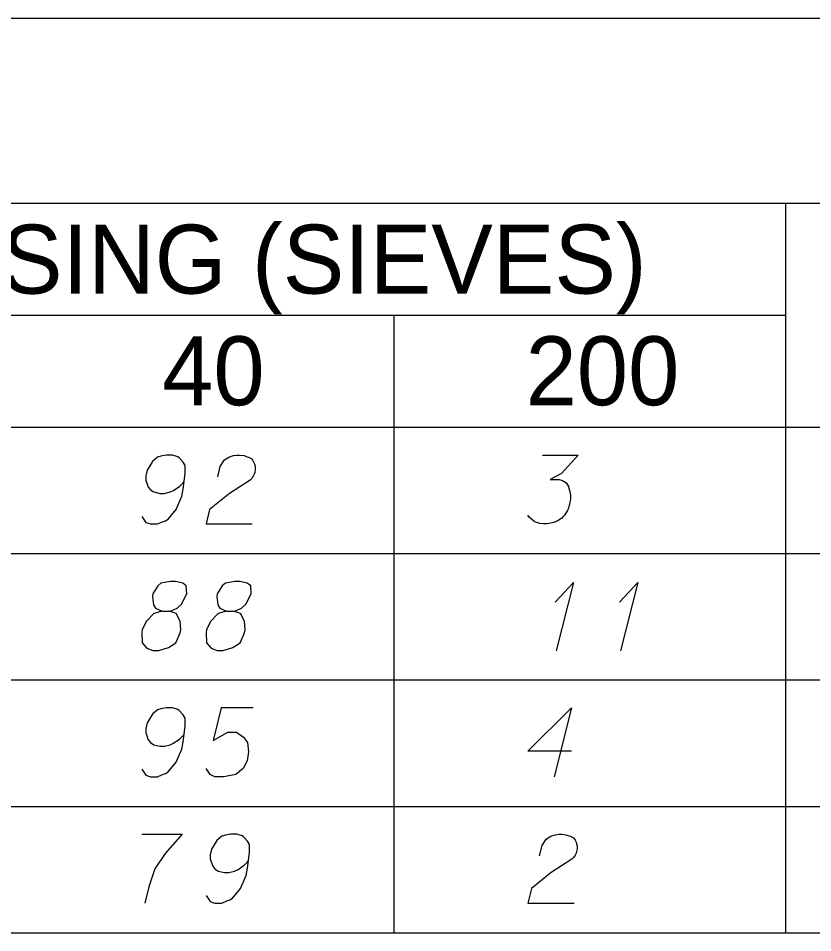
# Model space of a CAD drawing. Extents: x 2074207 to 2076812, y 516372 to 523312.
# Drawn here: x 2076678.5 to 2076733.8, y 516601.5 to 516665.2 of the extents above; entities that cross this region are included whole.
import ezdxf

# ---------------------------------------------------------------- set-up
doc = ezdxf.new("R2010")
doc.units = 0
for name, color, linetype in [('Prop DirtTable_ Soil Test Results - Outline (Major)', 7, 'Continuous'), ('Prop DirtTable_ Soil Test Results - Outline (Minor)', 7, 'Continuous'), ('Prop DirtTable_ Soil Test Results - Tx (Header - Small)', 7, 'Continuous'), ('Prop DirtTable_ Soil Test Results - Tx (Sample Data)', 7, 'Continuous')]:
    doc.layers.add(name, color=color, linetype=linetype)

msp = doc.modelspace()

# ---------------------------------------------------------------- linework, layer by layer
at = {"layer": 'Prop DirtTable_ Soil Test Results - Outline (Major)'}
for p, q in [((2076260.609, 516665.206), (2076811.903, 516665.206)), ((2076260.609, 516636.721), (2076811.903, 516636.721)), ((2076260.609, 516636.721), (2076811.903, 516636.721)), ((2076260.609, 516601.521), (2076811.903, 516601.521))]:
    msp.add_line(p, q, dxfattribs=at)
at = {"layer": 'Prop DirtTable_ Soil Test Results - Outline (Minor)'}
for p, q in [((2076260.609, 516652.321), (2076811.903, 516652.321)), ((2076731.93, 516652.321), (2076731.93, 516627.921)), ((2076526.074, 516644.521), (2076731.93, 516644.521)), ((2076704.671, 516644.521), (2076704.671, 516627.921)), ((2076260.609, 516627.921), (2076811.903, 516627.921)), ((2076260.609, 516627.921), (2076811.903, 516627.921)), ((2076704.671, 516627.921), (2076704.671, 516619.121)), ((2076731.93, 516627.921), (2076731.93, 516619.121)), ((2076260.609, 516619.121), (2076811.903, 516619.121)), ((2076260.609, 516619.121), (2076811.903, 516619.121)), ((2076704.671, 516619.121), (2076704.671, 516610.321)), ((2076731.93, 516619.121), (2076731.93, 516610.321)), ((2076260.609, 516610.321), (2076811.903, 516610.321)), ((2076260.609, 516610.321), (2076811.903, 516610.321)), ((2076704.671, 516610.321), (2076704.671, 516601.521)), ((2076731.93, 516610.321), (2076731.93, 516601.521)), ((2076260.609, 516601.521), (2076811.903, 516601.521))]:
    msp.add_line(p, q, dxfattribs=at)
at = {"layer": 'Prop DirtTable_ Soil Test Results - Tx (Sample Data)'}
for points in [[(2076687.116, 516630.515), (2076687.398, 516630.1), (2076687.715, 516629.986), (2076688.209, 516629.986), (2076688.562, 516630.137), (2076688.774, 516630.213), (2076688.95, 516630.326), (2076689.514, 516631.007), (2076689.902, 516631.914), (2076690.008, 516632.405), (2076690.149, 516633.501), (2076690.149, 516634.068), (2076690.008, 516634.295), (2076689.726, 516634.597), (2076689.62, 516634.673), (2076689.267, 516634.786), (2076688.809, 516634.786), (2076688.456, 516634.711), (2076688.209, 516634.635), (2076687.856, 516634.333), (2076687.504, 516633.728), (2076687.398, 516633.35), (2076687.398, 516633.048), (2076687.574, 516632.556), (2076687.715, 516632.367), (2076687.962, 516632.216), (2076688.386, 516632.103), (2076688.703, 516632.103), (2076689.091, 516632.216), (2076689.338, 516632.329), (2076689.761, 516632.632), (2076689.973, 516632.821), (2076690.079, 516632.934)], [(2076692.407, 516633.274), (2076692.583, 516633.992), (2076692.866, 516634.446), (2076693.183, 516634.635), (2076693.5, 516634.748), (2076693.747, 516634.786), (2076693.924, 516634.786), (2076694.241, 516634.748), (2076694.453, 516634.673), (2076694.559, 516634.635), (2076694.77, 516634.522), (2076694.876, 516634.37), (2076694.947, 516634.219), (2076694.982, 516634.106), (2076695.017, 516633.955), (2076695.017, 516633.766), (2076694.982, 516633.577), (2076694.947, 516633.463), (2076694.876, 516633.312), (2076694.77, 516633.161), (2076694.665, 516633.048), (2076693.218, 516632.103), (2076691.843, 516631.007), (2076691.596, 516629.986), (2076694.806, 516629.986)], [(2076715.019, 516634.786), (2076717.488, 516634.786), (2076716.324, 516633.501), (2076715.548, 516633.085), (2076716.183, 516633.085), (2076716.324, 516633.048), (2076716.394, 516633.01), (2076716.465, 516632.972), (2076716.535, 516632.934), (2076716.677, 516632.821), (2076716.747, 516632.707), (2076716.818, 516632.594), (2076716.853, 516632.481), (2076716.923, 516632.216), (2076716.959, 516631.989), (2076716.959, 516631.876), (2076716.959, 516631.725), (2076716.923, 516631.498), (2076716.888, 516631.347), (2076716.853, 516631.196), (2076716.818, 516631.082), (2076716.782, 516631.007), (2076716.747, 516630.931), (2076716.712, 516630.855), (2076716.641, 516630.742), (2076716.535, 516630.591), (2076716.43, 516630.478), (2076716.359, 516630.402), (2076716.253, 516630.326), (2076716.147, 516630.251), (2076716.006, 516630.175), (2076715.936, 516630.137), (2076715.689, 516630.062), (2076715.477, 516630.024), (2076715.336, 516629.986), (2076715.089, 516629.986), (2076714.807, 516630.024), (2076714.701, 516630.062), (2076714.595, 516630.1), (2076714.489, 516630.137), (2076714.384, 516630.213), (2076714.278, 516630.289), (2076714.101, 516630.44), (2076713.996, 516630.591)], [(2076688.527, 516623.907), (2076689.02, 516623.907), (2076689.162, 516623.945), (2076689.585, 516624.134), (2076689.902, 516624.437), (2076690.255, 516625.155), (2076690.22, 516625.684), (2076689.973, 516625.873), (2076689.479, 516625.986), (2076689.126, 516625.986), (2076688.456, 516625.873), (2076688.244, 516625.684), (2076687.892, 516625.117), (2076687.856, 516624.928), (2076687.927, 516624.361), (2076688.068, 516624.134), (2076688.527, 516623.907), (2076687.962, 516623.756), (2076687.433, 516623.189), (2076687.151, 516622.622), (2076687.116, 516622.433), (2076687.151, 516621.715), (2076687.468, 516621.337), (2076687.892, 516621.186), (2076688.315, 516621.186), (2076688.985, 516621.375), (2076689.479, 516621.715), (2076689.797, 516622.396), (2076689.832, 516622.622), (2076689.797, 516623.227), (2076689.514, 516623.756), (2076689.02, 516623.907)], [(2076693.007, 516623.907), (2076693.5, 516623.907), (2076693.642, 516623.945), (2076694.065, 516624.134), (2076694.382, 516624.437), (2076694.735, 516625.155), (2076694.7, 516625.684), (2076694.453, 516625.873), (2076693.959, 516625.986), (2076693.606, 516625.986), (2076692.936, 516625.873), (2076692.724, 516625.684), (2076692.372, 516625.117), (2076692.336, 516624.928), (2076692.407, 516624.361), (2076692.548, 516624.134), (2076693.007, 516623.907), (2076692.442, 516623.756), (2076691.913, 516623.189), (2076691.631, 516622.622), (2076691.596, 516622.433), (2076691.631, 516621.715), (2076691.948, 516621.337), (2076692.372, 516621.186), (2076692.795, 516621.186), (2076693.465, 516621.375), (2076693.959, 516621.715), (2076694.277, 516622.396), (2076694.312, 516622.622), (2076694.277, 516623.227), (2076693.994, 516623.756), (2076693.5, 516623.907)], [(2076715.9, 516624.55), (2076717.17, 516625.911), (2076715.971, 516621.148)], [(2076720.38, 516624.55), (2076721.65, 516625.911), (2076720.451, 516621.148)], [(2076687.116, 516612.915), (2076687.398, 516612.5), (2076687.715, 516612.386), (2076688.209, 516612.386), (2076688.562, 516612.537), (2076688.774, 516612.613), (2076688.95, 516612.726), (2076689.514, 516613.407), (2076689.902, 516614.314), (2076690.008, 516614.805), (2076690.149, 516615.901), (2076690.149, 516616.468), (2076690.008, 516616.695), (2076689.726, 516616.997), (2076689.62, 516617.073), (2076689.267, 516617.186), (2076688.809, 516617.186), (2076688.456, 516617.111), (2076688.209, 516617.035), (2076687.856, 516616.733), (2076687.504, 516616.128), (2076687.398, 516615.75), (2076687.398, 516615.448), (2076687.574, 516614.956), (2076687.715, 516614.767), (2076687.962, 516614.616), (2076688.386, 516614.503), (2076688.703, 516614.503), (2076689.091, 516614.616), (2076689.338, 516614.729), (2076689.761, 516615.032), (2076689.973, 516615.221), (2076690.079, 516615.334)], [(2076694.876, 516617.186), (2076692.654, 516617.186), (2076692.089, 516614.918), (2076693.112, 516615.485), (2076693.712, 516615.485), (2076694.206, 516615.145), (2076694.488, 516614.767), (2076694.559, 516614.125), (2076694.453, 516613.482), (2076694.171, 516612.953), (2076693.677, 516612.537), (2076692.83, 516612.386), (2076692.195, 516612.386), (2076691.878, 516612.537), (2076691.596, 516612.953)], [(2076717.029, 516614.163), (2076713.996, 516614.163), (2076717.029, 516617.186), (2076715.83, 516612.386)], [(2076687.116, 516608.386), (2076689.938, 516608.386), (2076689.761, 516608.197), (2076688.738, 516607.026), (2076688.033, 516605.967), (2076687.609, 516604.72), (2076687.327, 516603.586)], [(2076691.596, 516604.115), (2076691.878, 516603.7), (2076692.195, 516603.586), (2076692.689, 516603.586), (2076693.042, 516603.737), (2076693.254, 516603.813), (2076693.43, 516603.926), (2076693.994, 516604.607), (2076694.382, 516605.514), (2076694.488, 516606.005), (2076694.629, 516607.101), (2076694.629, 516607.668), (2076694.488, 516607.895), (2076694.206, 516608.197), (2076694.1, 516608.273), (2076693.747, 516608.386), (2076693.289, 516608.386), (2076692.936, 516608.311), (2076692.689, 516608.235), (2076692.336, 516607.933), (2076691.984, 516607.328), (2076691.878, 516606.95), (2076691.878, 516606.648), (2076692.054, 516606.156), (2076692.195, 516605.967), (2076692.442, 516605.816), (2076692.866, 516605.703), (2076693.183, 516605.703), (2076693.571, 516605.816), (2076693.818, 516605.929), (2076694.241, 516606.232), (2076694.453, 516606.421), (2076694.559, 516606.534)], [(2076714.807, 516606.874), (2076714.983, 516607.592), (2076715.266, 516608.046), (2076715.583, 516608.235), (2076715.9, 516608.348), (2076716.147, 516608.386), (2076716.324, 516608.386), (2076716.641, 516608.348), (2076716.853, 516608.273), (2076716.959, 516608.235), (2076717.17, 516608.122), (2076717.276, 516607.97), (2076717.347, 516607.819), (2076717.382, 516607.706), (2076717.417, 516607.555), (2076717.417, 516607.366), (2076717.382, 516607.177), (2076717.347, 516607.063), (2076717.276, 516606.912), (2076717.17, 516606.761), (2076717.065, 516606.648), (2076715.618, 516605.703), (2076714.243, 516604.607), (2076713.996, 516603.586), (2076717.206, 516603.586)]]:
    msp.add_lwpolyline(points, dxfattribs=at)

# ---------------------------------------------------------------- texts
at = {"layer": 'Prop DirtTable_ Soil Test Results - Tx (Header - Small)'}
for s, height, p in [('% PASSING (SIEVES)', 4.79998, (2076656.984, 516646.031)), ('40', 4.8, (2076688.534, 516638.256)), ('200', 4.8, (2076713.832, 516638.256))]:
    msp.add_text(s, height=height, dxfattribs=at).set_placement(p)

doc.saveas('drawing.dxf')
